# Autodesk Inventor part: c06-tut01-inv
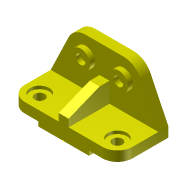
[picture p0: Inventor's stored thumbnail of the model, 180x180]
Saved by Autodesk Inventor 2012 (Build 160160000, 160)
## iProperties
Created: 2010-03
Part Number: c06-tut01-inv
Document SubType Name: Modeling
Designer: CADSoft
Density: 1 g/cm^3
Material: Default
Author: CADSoft
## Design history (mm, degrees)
sketch "Sketch1"
  geometry: 1 further point
sketch "Sketch2"
  geometry: L1 (108, 29)-(-108, 29); L2 (-108, 29)-(-108, 9); L3 (108, 9)-(108, 29); L4 (51, 9)-(51, 0); L5 (51, 0)-(-51, 0); L6 (-51, 0)-(-51, 9); L7 (-108, 9)-(-51, 9); L8 (51, 9)-(108, 9); 1 further point
  constraints: 16 end point, 4 vertical, 3 horizontal, 2 equal length, 1 midpoint
  dimensions: "d0" = 20 distance of L3.start L1.start; "d1" = 29 distance between parallel lines of L5 L1; "d2" = 102 distance of L4.end L5.end; "d3" = 57 distance of L4.start L3.start
extrude "Extrusion1" new body sketch "Sketch2" distance "d5" = 102; taper "d6" = 0 deg
sketch "Sketch3"
  geometry: L1 (108, -29)-(-108, -29) reference; L2 (108, -29)-(72.256, -103.447); L3 (38, -125)-(-38, -125); L4 (-72.256, -103.447)-(-108, -29); A1 r 38 centre (38, -87) between (38, -125) and (72.256, -103.447); A2 r 38 centre (-38, -87) between (-72.256, -103.447) and (-38, -125); 1 further point
  constraints: 6 end point, 4 point on circle, 4 tangent, 2 centre point, 1 equal length, 1 equal radius, 1 horizontal
  dimensions: "d9" = 96 distance between parallel lines of L1 L3; "d10" = 38 radius of A1; "d12" = 76 distance of A2.centre A1.centre
extrude "Extrusion2" join sketch "Sketch3" distance "d14" = 20; taper "d15" = 0 deg
sketch "Sketch4"
  geometry: C1 r 19 at (38, 87); C2 r 9.5 at (38, 87); C3 r 19 at (-38, 87); C4 r 9.5 at (-38, 87); A1 r 38 centre (-38, 87) between (-38, 125) and (-72.256, 103.447) reference; A2 r 38 centre (38, 87) between (72.256, 103.447) and (38, 125) reference; 1 further point
  constraints: 4 centre point, 4 coincident, 2 equal radius
  dimensions: "d16" = 38 diameter of C3; "d17" = 19 diameter of C4
extrude "Extrusion3" join sketch "Sketch4" distance "d18" = 10; taper "d19" = 0 deg
fillet "Fillet1" dims "d20" = 30
hole "Hole1" diameter "d23" = 20; stored, may be unused: countersink angle "d27" = 90 deg, drill point angle "d29" = 118 deg; dims "d21" = 10, "d22" = 10, "d24" = 6, "d25" = 38, "d26" = 6, "d28" = 8
hole "Hole2" diameter "d32" = 20; stored, may be unused: countersink angle "d36" = 90 deg, drill point angle "d38" = 118 deg; dims "d30" = 10, "d31" = 10, "d33" = 6, "d34" = 38, "d35" = 6, "d37" = 8
workplane "Work Plane1"
sketch "Sketch5"
  geometry: L1 (-40, 0)-(-40, -20); L2 (-40, -20)-(-15, -82); L3 (-15, -82)-(0, -82); L4 (-74.447, 0)-(0, 0) reference; L5 (0, -52)-(0, 0) reference; 2 further points
  constraints: 6 end point, 1 coincident, 1 point on line
  dimensions: "d40" = 40 distance between parallel lines of L5 L1; "d41" = 15 distance of L2.end L3.end; "d42" = 20 distance of L1.start L1.end
feature "Rib1" sketch "Sketch5" dims "d43" = 1, "d44" = 20, "d45" = 0
body "Solid1"
other parameters: "d39" = -108
